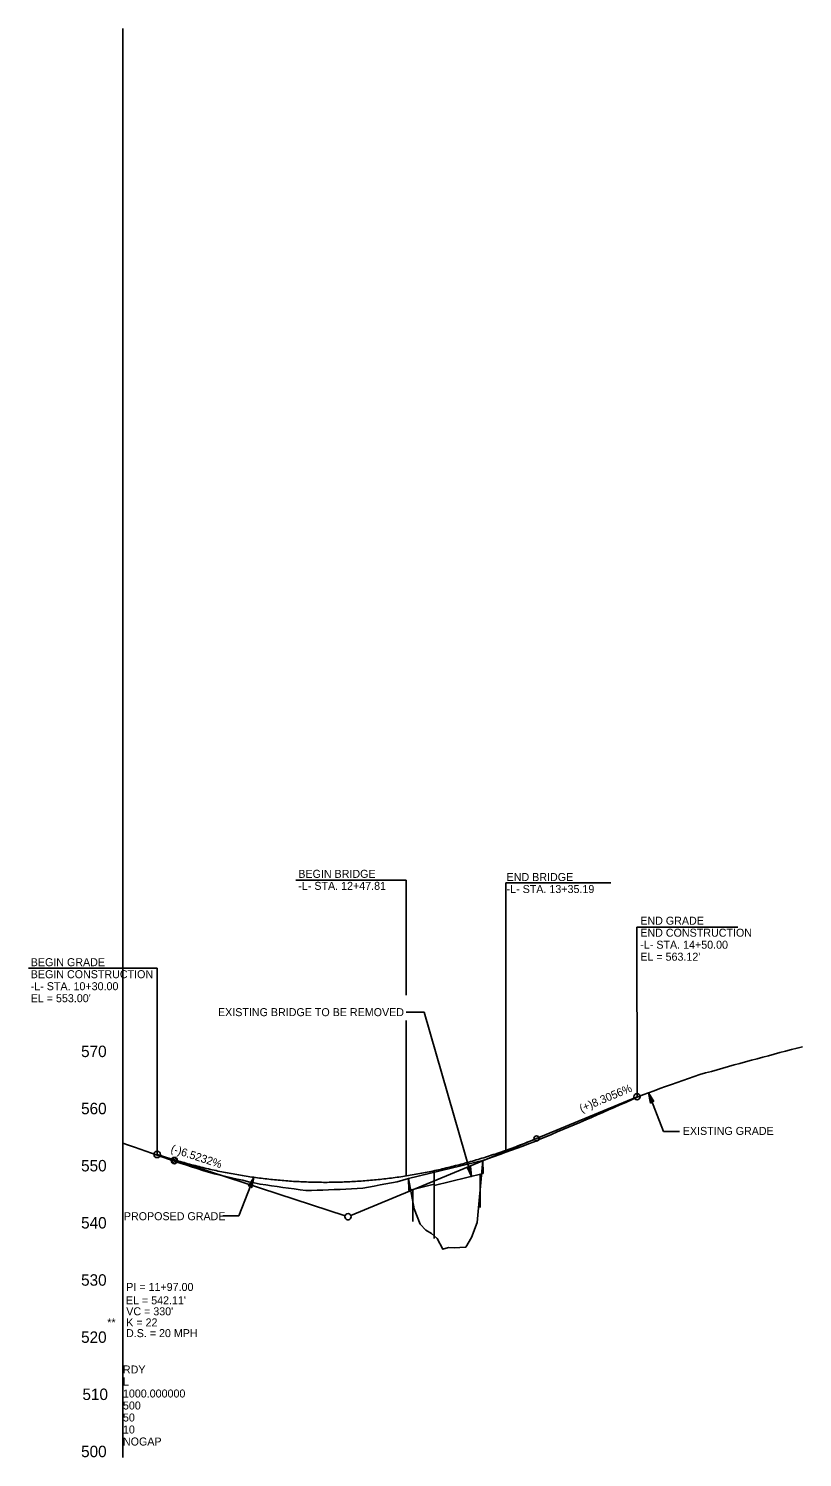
# Model space of a CAD drawing. Extents: x 1736530 to 1739201, y 695175 to 699135.
# Drawn here: x 1736530 to 1737207, y 697885 to 699135 of the extents above; entities that cross this region are included whole.
import ezdxf

# ---------------------------------------------------------------- set-up
doc = ezdxf.new("R2010")
doc.units = 0
for name, color, linetype in [('Default', 7, 'Continuous'), ('Exist Profile Cell', 7, 'Continuous'), ('Exist Vertical Profile Ground Line', 7, 'Continuous'), ('Exist Vertical Profile Vertical Axis Label', 7, 'Continuous'), ('Prop PFL Text', 7, 'Continuous'), ('Prop Terminator CELL', 7, 'Continuous'), ('Prop Vertical Profile Curve Label', 7, 'Continuous'), ('Prop Vertical Profile Grade', 7, 'Continuous'), ('Prop Vertical Profile Grade Label', 7, 'Continuous'), ('Prop VPI Label', 7, 'Continuous')]:
    doc.layers.add(name, color=color, linetype=linetype)

msp = doc.modelspace()

# ---------------------------------------------------------------- linework, layer by layer
at = {"layer": 'Default'}
for p, q in [((1736862.1, 698129.1), (1736927.1, 698145)), ((1736927.3, 698133.6), (1736927.1, 698145)), ((1736884.6, 698123.2), (1736884.4, 698134.6)), ((1736884.6, 698123.2), (1736927.3, 698133.6)), ((1736924.8, 698133), (1736924.8, 698103.7)), ((1736862.2, 698118.8), (1736862.1, 698129.1)), ((1736862.2, 698118.8), (1736884.6, 698124.3)), ((1736884.6, 698123.2), (1736884.6, 698076.7)), ((1736865.7, 698119.6), (1736865.7, 698091.7))]:
    msp.add_line(p, q, dxfattribs=at)
at = {"layer": 'Exist Profile Cell'}
msp.add_line((1736612.1, 697885.1), (1736612.1, 699135.1), dxfattribs=at)
at = {"layer": 'Exist Vertical Profile Ground Line'}
for points in [[(1737112.1, 698218.5), (1737117.1, 698220.1), (1737122.1, 698221.5), (1737127.1, 698222.9), (1737132.1, 698224.3), (1737137.1, 698225.7), (1737142.1, 698227.1), (1737147.1, 698228.5), (1737152.1, 698229.9), (1737157.1, 698231.3), (1737162.1, 698232.7), (1737167.1, 698234), (1737172.1, 698235.3), (1737177.1, 698236.6), (1737182.1, 698238), (1737187.1, 698239.3), (1737192.1, 698240.6), (1737197.1, 698242), (1737202.1, 698243.3), (1737206.8, 698244.4)], [(1736612.1, 698160.1), (1736617.1, 698158.4), (1736622.1, 698156.7), (1736627.1, 698154.9), (1736632.1, 698153.1), (1736637.1, 698151.4), (1736642.1, 698149.6), (1736647.1, 698147.9), (1736652.1, 698146.1), (1736657.1, 698144.4), (1736662.1, 698142.7), (1736667.1, 698141.1), (1736672.1, 698139.5), (1736677.1, 698137.9), (1736682.1, 698136.3), (1736687.1, 698134.7), (1736692.1, 698133.3), (1736697.1, 698132.2), (1736702.1, 698131), (1736707.1, 698129.9), (1736712.1, 698128.7), (1736717.1, 698127.6), (1736722.1, 698126.4), (1736727.1, 698125.3), (1736732.1, 698124.2), (1736737.1, 698123.5), (1736742.1, 698122.8), (1736747.1, 698122.1), (1736752.1, 698121.4), (1736757.1, 698120.8), (1736762.1, 698120.1), (1736767.1, 698119.4), (1736772.1, 698118.7), (1736777.1, 698118.7), (1736782.1, 698118.9), (1736787.1, 698119.1), (1736792.1, 698119.3), (1736797.1, 698119.5), (1736802.1, 698119.7), (1736807.1, 698119.9), (1736812.1, 698120.1), (1736817.1, 698120.3), (1736822.1, 698120.8), (1736827.1, 698121.7), (1736832.1, 698122.6), (1736837.1, 698123.5), (1736842.1, 698124.4), (1736847.1, 698125.4), (1736852.1, 698126.4), (1736857.1, 698127.8), (1736862.1, 698129.1), (1736867.1, 698102.6), (1736872.1, 698089.3), (1736877.1, 698083.9), (1736882.1, 698081.2), (1736887.1, 698076.8), (1736892.1, 698067.3), (1736897.1, 698068.8), (1736902.1, 698068.5), (1736907.1, 698068.7), (1736912.1, 698069), (1736917.1, 698077.7), (1736922.1, 698090.7), (1736927.1, 698145), (1736932.1, 698146.7), (1736937.1, 698148.5), (1736942.1, 698150.3), (1736947.1, 698152.1), (1736952.1, 698153.9), (1736957.1, 698155.7), (1736962.1, 698157.6), (1736967.1, 698159.4), (1736972.1, 698161.4), (1736977.1, 698163.5), (1736982.1, 698165.6), (1736987.1, 698167.8), (1736992.1, 698169.9), (1736997.1, 698172), (1737002.1, 698174.1), (1737007.1, 698176.2), (1737012.1, 698178.3), (1737017.1, 698180.4), (1737022.1, 698182.6), (1737027.1, 698184.8), (1737032.1, 698187), (1737037.1, 698189.2), (1737042.1, 698191.4), (1737047.1, 698193.6), (1737052.1, 698195.8), (1737057.1, 698198), (1737062.1, 698200.2), (1737067.1, 698202.4), (1737072.1, 698204.2), (1737077.1, 698206), (1737082.1, 698207.8), (1737087.1, 698209.6), (1737092.1, 698211.3), (1737097.1, 698213.1), (1737102.1, 698214.9), (1737107.1, 698216.7), (1737112.1, 698218.5)]]:
    msp.add_lwpolyline(points, dxfattribs=at)
at = {"layer": 'Prop Terminator CELL'}
for points in [[(1737076.8, 698196.4), (1737072.1, 698204.2), (1737073.9, 698195.2), (1737075, 698196.9)], [(1736913.3, 698139), (1736917.3, 698130.8), (1736916.4, 698140), (1736915.1, 698138.4)], [(1736721.9, 698122.4), (1736726.6, 698130.2), (1736724.8, 698121.2), (1736723.7, 698122.9)]]:
    msp.add_lwpolyline(points, close=True, dxfattribs=at)
at = {"layer": 'Prop Vertical Profile Curve Label'}
for centre in [(1736974.1, 698164.2), (1736657.1, 698144.9)]:
    msp.add_circle(centre, 2.25, dxfattribs=at)
at = {"layer": 'Prop Vertical Profile Grade'}
for p, q in [((1736974.1, 698164.2), (1737062.1, 698200.7)), ((1736642.1, 698150.2), (1736644.1, 698149.5))]:
    msp.add_line(p, q, dxfattribs=at)
msp.add_spline([(1736644.1, 698149.5), (1736650.7, 698147.4), (1736657.3, 698145.4), (1736663.9, 698143.5), (1736670.5, 698141.7), (1736677.1, 698140), (1736683.7, 698138.3), (1736690.3, 698136.8), (1736696.9, 698135.4), (1736703.5, 698134.1), (1736710.1, 698132.9), (1736716.7, 698131.7), (1736723.3, 698130.7), (1736729.9, 698129.8), (1736736.5, 698129), (1736743.1, 698128.2), (1736749.7, 698127.6), (1736756.3, 698127), (1736762.9, 698126.6), (1736769.5, 698126.3), (1736776.1, 698126), (1736782.7, 698125.9), (1736789.3, 698125.8), (1736795.9, 698125.9), (1736802.5, 698126), (1736809.1, 698126.3), (1736815.7, 698126.6), (1736822.3, 698127.1), (1736828.9, 698127.6), (1736835.5, 698128.2), (1736842.1, 698129), (1736848.7, 698129.8), (1736855.3, 698130.7), (1736861.9, 698131.8), (1736868.5, 698132.9), (1736875.1, 698134.1), (1736881.7, 698135.4), (1736888.3, 698136.8), (1736894.9, 698138.4), (1736901.5, 698140), (1736908.1, 698141.7), (1736914.7, 698143.5), (1736921.3, 698145.4), (1736927.9, 698147.4), (1736934.5, 698149.5), (1736941.1, 698151.7), (1736947.7, 698154), (1736954.3, 698156.4), (1736960.9, 698158.9), (1736967.5, 698161.5), (1736974.1, 698164.2)], degree=3, dxfattribs=at)
at = {"layer": 'Prop VPI Label'}
for p, q in [((1736859.9, 698390.3), (1736763.4, 698390.3)), ((1736859.9, 698289.5), (1736859.9, 698390.3)), ((1736947.3, 698153.9), (1736947.3, 698387.8)), ((1736947.3, 698387.8), (1737039.1, 698387.8)), ((1737062.1, 698200.7), (1737062, 698349.1)), ((1737062, 698349.1), (1737150.4, 698349.1)), ((1736529.5, 698313.2), (1736642.1, 698313.2)), ((1736642.1, 698150.2), (1736642.1, 698313.2)), ((1736859.9, 698274.7), (1736875.8, 698274.7)), ((1736917.3, 698130.8), (1736875.8, 698274.7)), ((1736859.9, 698131.4), (1736859.9, 698267.3)), ((1737072.1, 698204.2), (1737085.3, 698170.4)), ((1737085.3, 698170.4), (1737099.3, 698170.4)), ((1736974.1, 698164.2), (1736811.6, 698096.7)), ((1736644.1, 698149.5), (1736806.5, 698096.5)), ((1736726.6, 698130.2), (1736713.4, 698096.5)), ((1736713.4, 698096.5), (1736699.4, 698096.5))]:
    msp.add_line(p, q, dxfattribs=at)
for centre in [(1737062.1, 698200.7), (1737062.1, 698200.7), (1736642.1, 698150.2), (1736657.1, 698144.9), (1736809.1, 698095.7)]:
    msp.add_circle(centre, 2.75, dxfattribs=at)

# ---------------------------------------------------------------- texts
at = {"layer": 'Exist Profile Cell'}
for s, p in [('RDY', (1736612.1, 697958.6)), ('L', (1736612.1, 697948.1)), ('500', (1736612.1, 697927.1)), ('1000.000000', (1736612.1, 697937.6)), ('50', (1736612.1, 697916.6)), ('10', (1736612.1, 697906.1)), ('NOGAP', (1736612.1, 697895.6))]:
    msp.add_text(s, height=7, dxfattribs=at).set_placement(p)
at = {"layer": 'Exist Vertical Profile Vertical Axis Label'}
for s, p in [('570', (1736575.5, 698235.4)), ('560', (1736575.5, 698185.4)), ('550', (1736575.5, 698135.4)), ('540', (1736575.5, 698085.4)), ('530', (1736575.5, 698035.4)), ('520', (1736575.5, 697985.4)), ('510', (1736576.7, 697935.4)), ('500', (1736575.5, 697885.4))]:
    msp.add_text(s, height=10, dxfattribs=at).set_placement(p)
at = {"layer": 'Prop PFL Text'}
for s, p in [('BEGIN BRIDGE', (1736765.6, 698392.2)), ('END BRIDGE', (1736947.9, 698389.4)), ('-L- STA. 12+47.81', (1736765.6, 698381.7)), ('-L- STA. 13+35.19', (1736947.9, 698378.9)), ('END GRADE', (1737064.9, 698351.2)), ('END CONSTRUCTION', (1737064.9, 698340.7)), ('-L- STA. 14+50.00', (1737064.9, 698330.2)), ('BEGIN GRADE', (1736531.4, 698314.9)), ("EL = 563.12'", (1737064.9, 698319.7)), ('BEGIN CONSTRUCTION', (1736531.4, 698304.4)), ('-L- STA. 10+30.00', (1736531.4, 698293.9)), ("EL = 553.00'", (1736531.4, 698283.4)), ('EXISTING BRIDGE TO BE REMOVED', (1736695.3, 698271.2)), ('EXISTING GRADE', (1737102.1, 698167.3)), ('PROPOSED GRADE', (1736612.9, 698092.7))]:
    msp.add_text(s, height=7, dxfattribs=at).set_placement(p)
at = {"layer": 'Prop Vertical Profile Curve Label'}
for s, p in [("VC = 330'", (1736615, 698009.5)), ('**', (1736598.4, 697999.8)), ('D.S. = 20 MPH', (1736614.8, 697990.4)), ('K = 22', (1736615, 697999.8))]:
    msp.add_text(s, height=7, dxfattribs=at).set_placement(p)
at = {"layer": 'Prop Vertical Profile Grade Label'}
for s, rotation, p in [('(+)8.3056%', 22.5522, (1737013.4, 698186.9)), ('(-)6.5232%', 341.9357, (1736653.4, 698152.4))]:
    msp.add_text(s, height=7, rotation=rotation, dxfattribs=at).set_placement(p)
at = {"layer": 'Prop VPI Label'}
for s, p in [('PI = 11+97.00', (1736615, 698030.8)), ("EL = 542.11'", (1736614.7, 698019.1))]:
    msp.add_text(s, height=7, dxfattribs=at).set_placement(p)

doc.saveas('drawing.dxf')
